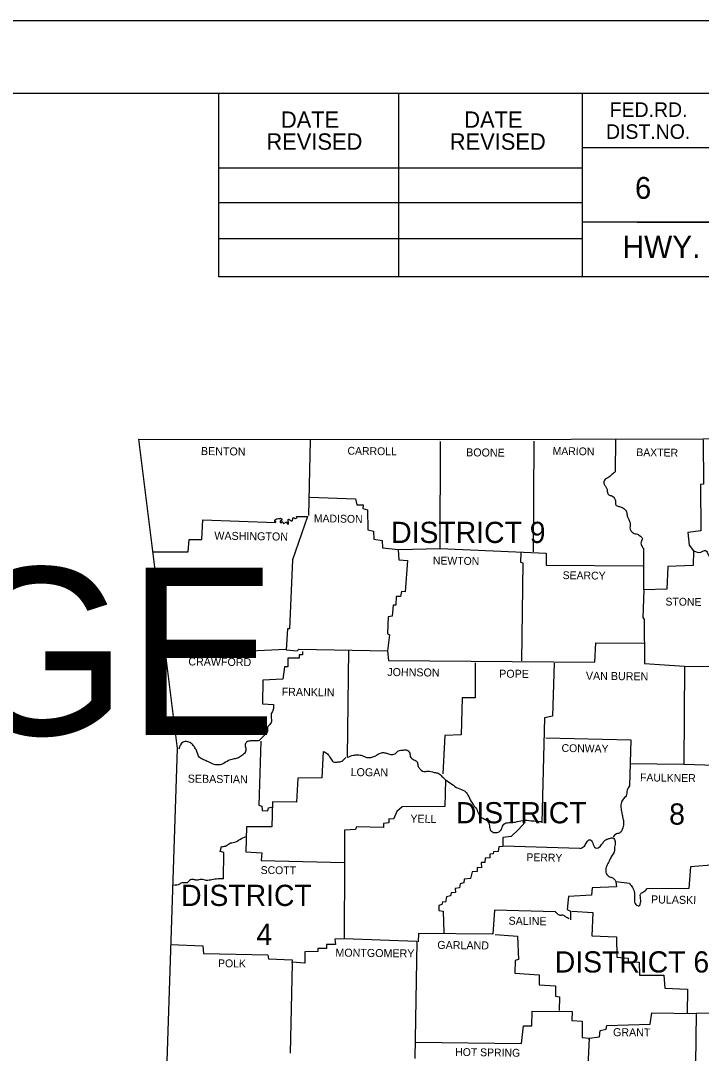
# Model space of a CAD drawing. Extents: x 79818 to 83933, y 50884 to 53307.
# Drawn here: x 83152 to 83518, y 52752 to 53307 of the extents above; entities that cross this region are included whole.
import ezdxf

# ---------------------------------------------------------------- set-up
doc = ezdxf.new("R2010")
doc.units = 0
for name, color, linetype in [('Default', 7, 'Continuous'), ('R_Border', 7, 'Continuous'), ('R_Border Notes', 7, 'Continuous'), ('R_No Plot', 7, 'Continuous')]:
    doc.layers.add(name, color=color, linetype=linetype)

msp = doc.modelspace()

# ---------------------------------------------------------------- linework, layer by layer
at = {"layer": 'Default'}
msp.add_line((83365.57, 52812.38), (83364.41, 52749.58), dxfattribs=at)
for points in [[(83215.87, 53082.48), (83377.57, 53082.38), (83519.47, 53082.68), (83686.87, 53085.28), (83764.47, 53087.08)], [(83215.87, 53082.48), (83236.57, 52916.28), (83227.57, 52644.98)], [(83472.37, 53082.08), (83472.17, 53064.98)], [(83519.47, 53082.08), (83519.67, 53058.28), (83517.97, 53058.18), (83518.27, 53033.28), (83511.27, 53032.28), (83511.87, 53025.58), (83514.27, 53022.48), (83514.07, 53014.58), (83500.47, 53014.08), (83499.97, 53001.88), (83487.57, 53001.48), (83486.97, 52986.68), (83487.67, 52985.48), (83487.97, 52961.88), (83509.37, 52960.48), (83509.07, 52907.78), (83526.07, 52907.28), (83526.07, 52853.68), (83512.67, 52852.68), (83511.67, 52840.88), (83489.17, 52840.78)], [(83308.17, 53081.88), (83307.27, 53041.38)], [(83307.97, 53051.28), (83332.57, 53050.48), (83333.17, 53047.28), (83336.57, 53047.18), (83336.47, 53045.18), (83338.87, 53044.58), (83339.07, 53033.68), (83342.17, 53032.98), (83342.37, 53028.68), (83346.77, 53028.08), (83346.97, 53024.08), (83355.67, 53023.18), (83378.07, 53023.68), (83378.27, 53081.18)], [(83428.37, 53081.38), (83428.07, 53021.98)], [(83223.77, 53021.98), (83242.47, 53021.88), (83242.97, 53028.48), (83249.87, 53028.48), (83250.47, 53039.18), (83289.47, 53037.78)], [(83300.81, 53040.84), (83306.77, 53040.88), (83298.67, 53017.68), (83297.07, 52980.58), (83295.87, 52980.48), (83295.27, 52969.28), (83301.17, 52968.78), (83302.07, 52969.68), (83349.77, 52968.78), (83350.27, 52963.48)], [(83355.47, 53022.98), (83355.87, 53017.58), (83360.47, 53017.28), (83359.27, 53000.48), (83357.17, 53000.58), (83356.77, 52997.88), (83354.37, 52997.88), (83354.27, 52993.28), (83352.77, 52993.18), (83352.27, 52987.28), (83350.07, 52986.98), (83349.77, 52977.98), (83350.77, 52977.28), (83349.77, 52968.78)], [(83378.07, 53023.68), (83435.07, 53021.28), (83434.97, 53014.78), (83487.27, 53014.38)], [(83421.37, 53021.58), (83421.27, 53016.38), (83422.57, 53016.08), (83421.77, 52963.28)], [(83487.57, 53001.48), (83487.47, 53023.98)], [(83350.27, 52963.48), (83461.27, 52962.58), (83461.77, 52973.08), (83487.57, 52972.78)], [(83230.37, 52969.18), (83275.87, 52967.08), (83276.07, 52968.68), (83295.07, 52969.58)], [(83304.07, 52968.38), (83304.07, 52966.58), (83302.17, 52966.58), (83302.27, 52964.78), (83296.17, 52964.68), (83296.07, 52960.18), (83294.37, 52960.18), (83293.47, 52953.48), (83282.67, 52952.98), (83282.57, 52940.28), (83288.37, 52939.88)], [(83328.77, 52969.18), (83328.07, 52911.48)], [(83396.9, 52962.21), (83396.8, 52943.51), (83389.9, 52943.41), (83389.3, 52923.51), (83380.5, 52923.21), (83379.5, 52902.61)], [(83439.26, 52962.11), (83438.52, 52933.51), (83434.13, 52932.78), (83432.66, 52876.32)], [(83509.37, 52960.48), (83560.77, 52960.18), (83565.17, 52962.28), (83564.87, 52923.18), (83561.87, 52921.88), (83559.17, 52919.58), (83558.27, 52918.68), (83558.17, 52907.48), (83525.47, 52907.48)], [(83434.77, 52921.88), (83480.47, 52920.78), (83479.87, 52896.08)], [(83281.57, 52920.08), (83280.57, 52885.68), (83282.07, 52885.28), (83282.37, 52882.88), (83285.37, 52882.68), (83285.67, 52884.38), (83288.07, 52884.78)], [(83315.17, 52914.68), (83314.47, 52900.38), (83301.47, 52900.28), (83300.77, 52887.28), (83287.87, 52887.58), (83287.47, 52874.18), (83273.97, 52874.08), (83273.57, 52860.68), (83282.07, 52860.18), (83281.77, 52856.08), (83326.51, 52854.84)], [(83479.97, 52908.18), (83509.07, 52907.78)], [(83380.87, 52899.38), (83380.47, 52884.98), (83357.67, 52884.88), (83354.67, 52882.28), (83352.97, 52878.28), (83350.47, 52878.48), (83350.37, 52876.18), (83347.47, 52875.88), (83347.57, 52873.78), (83333.07, 52874.18), (83332.57, 52872.58), (83326.57, 52872.38), (83326.51, 52854.84)], [(83423.77, 52876.58), (83420.17, 52872.68), (83416.27, 52868.98), (83411.77, 52868.28), (83411.77, 52863.58), (83409.57, 52863.28), (83409.17, 52860.88), (83406.67, 52860.68), (83406.47, 52859.58), (83404.77, 52859.48), (83404.67, 52857.38), (83402.27, 52857.28), (83402.07, 52854.88), (83400.07, 52854.88), (83400.17, 52852.08), (83397.97, 52852.28), (83397.87, 52850.08), (83395.17, 52849.88), (83394.37, 52846.28), (83390.97, 52845.98), (83390.67, 52843.98), (83388.87, 52843.48), (83388.37, 52841.38), (83386.07, 52840.88), (83386.27, 52838.78), (83383.97, 52838.58), (83383.57, 52836.98), (83381.47, 52836.38), (83380.97, 52833.68), (83379.37, 52833.78), (83378.87, 52832.38), (83377.37, 52831.88), (83377.27, 52829.18), (83379.57, 52828.78), (83379.97, 52817.18)], [(83261.47, 52846.18), (83261.77, 52860.28), (83259.77, 52860.88), (83260.37, 52863.58)], [(83453.07, 52862.38), (83411.87, 52863.68)], [(83326.51, 52854.84), (83326.37, 52814.02)], [(83479.77, 52843.68), (83472.57, 52844.48), (83472.87, 52841.78), (83459.77, 52841.28), (83459.37, 52837.38), (83447.07, 52836.68), (83446.37, 52829.68), (83448.17, 52828.78), (83448.17, 52824.18)], [(83439.97, 52828.38), (83407.27, 52829.38), (83406.37, 52816.48), (83366.37, 52816.68), (83366.21, 52812.36)], [(83448.87, 52828.68), (83460.07, 52827.98), (83459.67, 52815.48), (83472.77, 52814.98), (83472.97, 52804.08), (83479.17, 52803.58), (83479.17, 52801.68), (83484.97, 52801.28), (83485.17, 52794.28), (83498.37, 52794.28), (83498.77, 52787.38), (83510.97, 52786.78), (83510.87, 52773.78)], [(83407.57, 52816.28), (83419.67, 52815.38), (83420.07, 52802.78), (83418.37, 52802.18), (83418.17, 52795.48), (83431.27, 52794.58), (83431.27, 52789.08), (83439.97, 52788.58), (83440.07, 52783.08), (83442.17, 52782.78), (83442.07, 52775.38)], [(83233.07, 52810.78), (83250.37, 52810.18), (83250.77, 52805.98), (83285.37, 52805.28), (83285.77, 52803.08), (83298.37, 52802.68), (83298.27, 52800.78)], [(83326.37, 52814.02), (83326.37, 52813.88), (83321.37, 52813.78), (83321.77, 52810.78), (83316.97, 52810.88), (83316.87, 52808.68), (83312.17, 52808.68), (83312.27, 52807.08), (83305.27, 52806.88), (83305.17, 52800.78), (83298.38, 52801.38)], [(83365.57, 52812.38), (83326.37, 52813.88)], [(83298.36, 52800.6), (83297.28, 52752.38)], [(83630.17, 52785.28), (83592.37, 52786.28), (83592.17, 52773.98), (83515.68, 52773.68)], [(83364.57, 52758.38), (83421.77, 52757.58), (83422.87, 52767.08), (83427.37, 52767.08), (83427.47, 52775.08), (83449.07, 52774.78), (83448.87, 52769.98), (83454.47, 52769.58), (83454.47, 52760.78), (83458.07, 52760.48), (83458.03, 52759.57)], [(83458.07, 52760.48), (83463.67, 52761.28), (83464.07, 52764.68), (83467.37, 52765.28), (83467.57, 52767.28), (83490.87, 52767.98), (83491.77, 52774.08), (83515.67, 52773.68)], [(83515.68, 52773.68), (83515.07, 52733.08), (83512.77, 52732.98), (83512.47, 52707.88)], [(83458.07, 52760.48), (83456.87, 52734.28), (83455.97, 52734.58), (83456.07, 52720.98)]]:
    msp.add_lwpolyline(points, dxfattribs=at)
for centre, radius, start, end in [((83289.03, 53038.51), 0.176, 156.045, 216.8602), ((83289.11, 53038.47), 0.263, 125.5472, 156.045), ((83289.39, 53038.77), 0.62, 216.8602, 248.1917), ((83293.66, 53035.01), 5.97, 135.8747, 141.9374), ((83289.2, 53038.3), 0.113, 248.1917, 347.1581), ((83289.42, 53038.25), 0.113, 39.7957, 167.1581), ((83292.02, 53034.04), 5.76, 111.5873, 117.3149), ((83289.42, 53038), 0.196, 286.231, 356.4249), ((83289.14, 53038.02), 0.473, 356.4249, 39.7957), ((83291.17, 53036.02), 3.61, 102.7546, 110.6543), ((83294.11, 53019.48), 20.41, 96.7932, 100.5516), ((83292.09, 53037.92), 1.87, 89.3336, 102.0989), ((83292.57, 53038.08), 0.631, 132.41, 167.3343), ((83293.75, 53038.55), 1.82, 190.4879, 208.8781), ((83292.09, 53038.17), 1.62, 66.564, 89.3336), ((83292.39, 53038.43), 0.273, 68.1414, 155.5454), ((83292.38, 53037.93), 0.349, 229.2667, 280.0802), ((83292.5, 53037.91), 0.322, 259.6916, 298.8193), ((83292.59, 53038.94), 0.273, 248.0969, 311.8879), ((83292.53, 53037.84), 0.247, 298.8193, 356.0222), ((83292.44, 53038.98), 0.734, 32.4621, 66.564), ((83291.95, 53039.66), 1.24, 311.8879, 335.7798), ((83293.02, 53037.81), 0.247, 110.8612, 176.0222), ((83292.98, 53037.93), 0.114, 67.373, 110.8611), ((83292.33, 53036.37), 1.8, 56.6801, 67.373), ((83292.86, 53039.25), 0.235, 335.7798, 32.4621), ((83292.91, 53037.27), 0.733, 31.4192, 56.6801), ((83294.12, 53037.76), 0.593, 190.5048, 239.8098), ((83295.03, 53037), 0.641, 103.7654, 132.9836), ((83295.79, 53033.88), 3.85, 94.9715, 103.7654), ((83295.48, 53037.47), 0.251, 60.0097, 94.9715), ((83295.48, 53037.47), 0.248, 333.5484, 60.0097), ((83296.84, 53038.79), 0.734, 133.169, 186.7209), ((83297.7, 53038.89), 1.6, 186.725, 211.1186), ((83293.96, 53037.25), 2.51, 356.1873, 18.9181), ((83296.63, 53038.84), 0.561, 84.2874, 120.9726), ((83296.65, 53039.05), 0.354, 25.1247, 84.2874), ((83297.21, 53039.38), 0.302, 217.103, 260.4946), ((83302.05, 53045.83), 8.33, 234.0433, 240.9011), ((83298.06, 53038.79), 0.246, 254.84, 285.5846), ((83298.23, 53038.94), 0.405, 255.9788, 27.04), ((83298.81, 53039.26), 0.256, 131.9339, 211.1431), ((83299.44, 53039.6), 0.819, 165.762, 190.3593), ((83299.27, 53039.82), 0.623, 152.9692, 181.5409), ((83299.1, 53038.65), 1.49, 70.6596, 104.9036), ((83300.44, 53041.83), 1.96, 244.3985, 264.9644), ((83300.23, 53041.73), 1.85, 271.1237, 284.041), ((83300.65, 53040.08), 0.151, 284.041, 330.4698), ((83300.15, 53040.85), 1.05, 306.5402, 333.8685), ((83300.43, 53040.28), 0.67, 9.5116, 55.9405), ((83293.97, 53038.13), 0.904, 260.462, 312.7214), ((83295.99, 53037.37), 0.285, 181.1358, 232.5966), ((83297.22, 53037.8), 1.56, 205.0092, 220.2264), ((83296.11, 53036.78), 0.0792, 169.0691, 214.0773), ((83296.08, 53037.12), 0.387, 265.2347, 310.2463), ((83296.09, 53037.11), 0.372, 310.2463, 356.1873)]:
    msp.add_arc(centre, radius, start, end, dxfattribs=at)
for points in [[(83472.17, 53064.98), (83470.37, 53063.48), (83468.77, 53062.08), (83466.37, 53060.38), (83466.07, 53058.78), (83466.87, 53057.18), (83467.67, 53055.88), (83467.97, 53054.08), (83468.67, 53052.58), (83470.37, 53051.98), (83471.77, 53050.68), (83472.27, 53048.88), (83472.47, 53047.18), (83474.07, 53046.38), (83475.87, 53045.78), (83477.57, 53044.58), (83478.37, 53043.08), (83478.57, 53041.18), (83479.27, 53039.68), (83480.07, 53037.88), (83480.27, 53036.38), (83480.07, 53034.88), (83480.47, 53033.48), (83481.77, 53032.08), (83484.07, 53031.38), (83485.67, 53030.38), (83486.77, 53028.98), (83486.07, 53027.28), (83486.17, 53025.78), (83487.07, 53023.98)], [(83514.27, 53022.48), (83518.27, 53021.78), (83520.67, 53022.68), (83522.37, 53020.08), (83523.27, 53018.08), (83524.77, 53015.18), (83527.17, 53014.28), (83528.97, 53012.68), (83528.97, 53010.98), (83527.37, 53009.38), (83526.17, 53007.78), (83526.57, 53005.88), (83526.97, 53003.28), (83526.97, 53000.78), (83526.37, 52998.48), (83525.87, 52996.38), (83526.37, 52994.58), (83528.27, 52994.88), (83530.27, 52996.38), (83532.37, 52996.38), (83534.37, 52995.28), (83536.47, 52993.38), (83538.57, 52993.78), (83540.27, 52994.28), (83542.67, 52994.98), (83544.37, 52994.08), (83545.87, 52992.88), (83547.67, 52990.98), (83549.37, 52989.78), (83551.57, 52988.68), (83554.27, 52987.98), (83556.77, 52986.28), (83557.17, 52983.38), (83557.07, 52980.88), (83556.87, 52977.78), (83556.67, 52974.38), (83556.97, 52971.08), (83558.07, 52968.88), (83559.47, 52966.28), (83559.87, 52963.88), (83559.77, 52960.08)], [(83288.37, 52939.88), (83288.37, 52937.78), (83287.57, 52935.58), (83287.07, 52933.68), (83287.37, 52931.18), (83286.47, 52929.18), (83285.17, 52927.58), (83285.17, 52925.58), (83283.67, 52923.48), (83282.07, 52921.88), (83280.67, 52920.58), (83278.17, 52920.38), (83276.07, 52920.28), (83273.97, 52919.58), (83273.17, 52918.08), (83273.57, 52915.78), (83272.77, 52913.58), (83270.67, 52911.88), (83268.37, 52910.78), (83265.97, 52910.38), (83262.67, 52908.78), (83259.67, 52907.48), (83256.47, 52907.68), (83253.47, 52908.98), (83250.77, 52910.18), (83248.67, 52911.38), (83246.97, 52915.08), (83245.87, 52917.08), (83243.97, 52919.08), (83241.67, 52919.88), (83239.77, 52919.68), (83237.47, 52915.78)], [(83328.07, 52911.48), (83331.37, 52912.58), (83333.77, 52912.78), (83336.17, 52912.38), (83338.67, 52911.38), (83341.37, 52911.58), (83343.37, 52912.28), (83345.37, 52913.58), (83347.57, 52913.98), (83349.67, 52913.58), (83351.87, 52912.98), (83354.27, 52913.68), (83355.67, 52914.98), (83358.07, 52915.38), (83360.17, 52915.38), (83361.67, 52913.68), (83361.97, 52911.88), (83363.87, 52910.18), (83365.57, 52909.08), (83366.07, 52906.98), (83366.97, 52905.48), (83367.87, 52904.48), (83369.17, 52903.88), (83371.37, 52904.08), (83374.77, 52903.38), (83376.97, 52902.88), (83378.97, 52901.18), (83380.87, 52899.38)], [(83315.17, 52914.68), (83317.37, 52913.28), (83319.07, 52910.98), (83320.57, 52909.08), (83323.07, 52908.98), (83325.07, 52909.38), (83327.37, 52911.38)], [(83380.87, 52899.38), (83384.37, 52896.98), (83387.67, 52894.88), (83391.07, 52893.38), (83392.97, 52891.18), (83394.67, 52887.78), (83396.07, 52885.68), (83397.87, 52883.08), (83399.17, 52880.18), (83401.27, 52878.58), (83403.47, 52877.18), (83404.57, 52874.68), (83405.07, 52872.18), (83407.47, 52870.98), (83409.77, 52871.48), (83411.07, 52872.98), (83412.27, 52875.58), (83414.97, 52876.38), (83418.47, 52876.68), (83422.47, 52877.58), (83426.87, 52877.38), (83433.07, 52876.98)], [(83479.87, 52896.08), (83478.57, 52893.78), (83477.97, 52890.78), (83476.37, 52888.88), (83475.37, 52886.68), (83475.27, 52883.78), (83475.77, 52881.18), (83476.27, 52878.68), (83476.67, 52876.38), (83476.17, 52873.48), (83474.87, 52870.98), (83472.87, 52870.28), (83470.97, 52868.58)], [(83260.37, 52863.58), (83262.57, 52863.78), (83264.67, 52865.18), (83267.47, 52865.78), (83270.27, 52867.28), (83273.77, 52868.88)], [(83453.07, 52862.38), (83455.57, 52863.78), (83456.87, 52865.88), (83458.47, 52867.18), (83460.07, 52865.38), (83461.47, 52862.78), (83462.97, 52862.78), (83464.87, 52864.58), (83466.07, 52866.18), (83467.57, 52867.38), (83469.17, 52867.88), (83470.87, 52868.08), (83472.17, 52866.18), (83471.77, 52863.18), (83471.77, 52861.18), (83470.67, 52859.08), (83469.47, 52856.88), (83468.17, 52854.38), (83467.17, 52851.68), (83467.37, 52849.08), (83468.77, 52847.38), (83470.37, 52846.88), (83472.57, 52844.68)], [(83261.47, 52846.18), (83258.57, 52846.08), (83255.27, 52845.68), (83252.27, 52845.28), (83249.57, 52845.78), (83247.07, 52845.38), (83245.37, 52845.78), (83243.27, 52845.28), (83242.07, 52844.08), (83239.57, 52844.08), (83237.77, 52843.28), (83234.87, 52842.58)], [(83479.77, 52843.68), (83481.47, 52841.48), (83482.47, 52838.48), (83482.47, 52835.08), (83483.27, 52832.28), (83484.87, 52831.68), (83485.87, 52834.08), (83485.67, 52836.48), (83485.67, 52837.88), (83487.37, 52839.08), (83489.17, 52840.78)], [(83447.47, 52824.68), (83445.57, 52825.68), (83444.07, 52826.58), (83442.47, 52826.48), (83441.17, 52827.28), (83439.97, 52828.38)]]:
    msp.add_spline(points, degree=3, dxfattribs=at)
at = {"layer": 'R_Border'}
for p, q in [((80723.6, 53268.52), (83885.4, 53268.52)), ((83259, 53169.72), (83259, 53268.52)), ((83355.8, 53169.72), (83355.8, 53268.52)), ((83454.4, 53268.52), (83454.4, 53169.72)), ((83885.4, 53239.12), (83454.4, 53239.12)), ((83259, 53228.32), (83454.4, 53228.32)), ((83259, 53209.72), (83454.4, 53209.72)), ((83885.4, 53199.12), (83454.4, 53199.12)), ((83484, 53199.12), (83885.4, 53199.12)), ((83259, 53190.32), (83454.4, 53190.32)), ((83885.4, 53169.72), (83259, 53169.72))]:
    msp.add_line(p, q, dxfattribs=at)
at = {"layer": 'R_No Plot'}
msp.add_line((80599.59, 53307.47), (83932.93, 53307.47), dxfattribs=at)
msp.add_lwpolyline([(80599.53, 53307.47), (83932.93, 53307.47), (83932.93, 51174.09), (80599.53, 51174.09)], close=True, dxfattribs=at)

# ---------------------------------------------------------------- texts
at = {"layer": 'Default'}
for s, height, rotation, p in [('BENTON', 4.301, 359.2527, (83249.37, 53073.98)), ('CARROLL', 4.201, 359.1481, (83328.17, 53074.18)), ('BOONE', 4.301, 359.4001, (83391.97, 53073.28)), ('MARION', 4.201, 359.1854, (83438.47, 53074.08)), ('BAXTER', 4.201, 359.2559, (83483.47, 53073.38)), ('MADISON', 4.201, 359.0906, (83310.07, 53037.88)), ('WASHINGTON', 4.3, 359.232, (83256.57, 53028.48)), ('NEWTON', 4.201, 359.2717, (83374.07, 53015.18)), ('SEARCY', 4.199, 359.2527, (83443.87, 53007.28)), ('STONE', 4.199, 359.4001, (83499.17, 52993.08)), ('CRAWFORD', 4.299, 359.2771, (83242.57, 52960.88)), ('JOHNSON', 4.301, 359.3514, (83349.57, 52955.18)), ('POPE', 4.301, 359.6155, (83409.77, 52954.28)), ('VAN BUREN', 4.301, 359.3508, (83456.37, 52953.18)), ('FRANKLIN', 4.301, 359.1815, (83292.77, 52944.58)), ('CONWAY', 4.199, 359.0371, (83443.27, 52914.38)), ('LOGAN', 4.301, 359.3969, (83329.87, 52901.38)), ('SEBASTIAN', 4.299, 359.2816, (83242.27, 52897.88)), ('FAULKNER', 4.201, 359.2486, (83485.47, 52898.58)), ('YELL', 4.301, 359.1987, (83361.97, 52876.38)), ('PERRY', 4.2, 359.0858, (83424.37, 52855.68)), ('SCOTT', 4.201, 359.4063, (83281.47, 52848.78)), ('PULASKI', 4.301, 359.053, (83491.37, 52832.98)), ('SALINE', 4.301, 359.1491, (83414.77, 52821.48)), ('GARLAND', 4.301, 359.3658, (83376.47, 52808.48)), ('MONTGOMERY', 4.301, 359.2944, (83321.67, 52804.38)), ('POLK', 4.199, 359.2152, (83258.57, 52798.68)), ('GRANT', 4.301, 359.4032, (83470.97, 52761.58)), ('HOT SPRING', 4.201, 359.2216, (83386.07, 52750.98))]:
    msp.add_text(s, height=height, rotation=rotation, dxfattribs=at).set_placement(p)
for s, height, p in [('DISTRICT 9', 11.4, (83351.67, 53026.68)), ('HWY.  301 FLOOD DAMAGE', 89.9998, (81705.17, 52923.47)), ('DISTRICT', 11.4, (83386.47, 52875.98)), ('8', 11.4, (83501.17, 52875.28)), ('DISTRICT', 11.4, (83238.72, 52831.56)), ('4', 11.4, (83279.22, 52810.56)), ('DISTRICT 6', 11.4, (83439.67, 52795.78))]:
    msp.add_text(s, height=height, dxfattribs=at).set_placement(p)
at = {"layer": 'R_Border'}
for s, height, p in [('FED.RD.', 7.819, (83469.2, 53255.72)), ('DATE', 8.792, (83292.38, 53249.88)), ('DATE', 8.792, (83390.98, 53249.88)), ('DIST.NO.', 7.819, (83467.2, 53243.92)), ('REVISED', 8.792, (83284.58, 53238.08)), ('REVISED', 8.792, (83383.18, 53238.08)), ('6', 11.72, (83482.8, 53211.72))]:
    msp.add_text(s, height=height, dxfattribs=at).set_placement(p)
at = {"layer": 'R_Border Notes'}
msp.add_text('HWY. 301 FLOOD DAMAGE REPAIRS (PIKE CO.) (S)', height=12, dxfattribs=at).set_placement((83476.09, 53179.92))

doc.saveas('drawing.dxf')
